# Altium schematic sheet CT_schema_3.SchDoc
size 362 x 192 mm
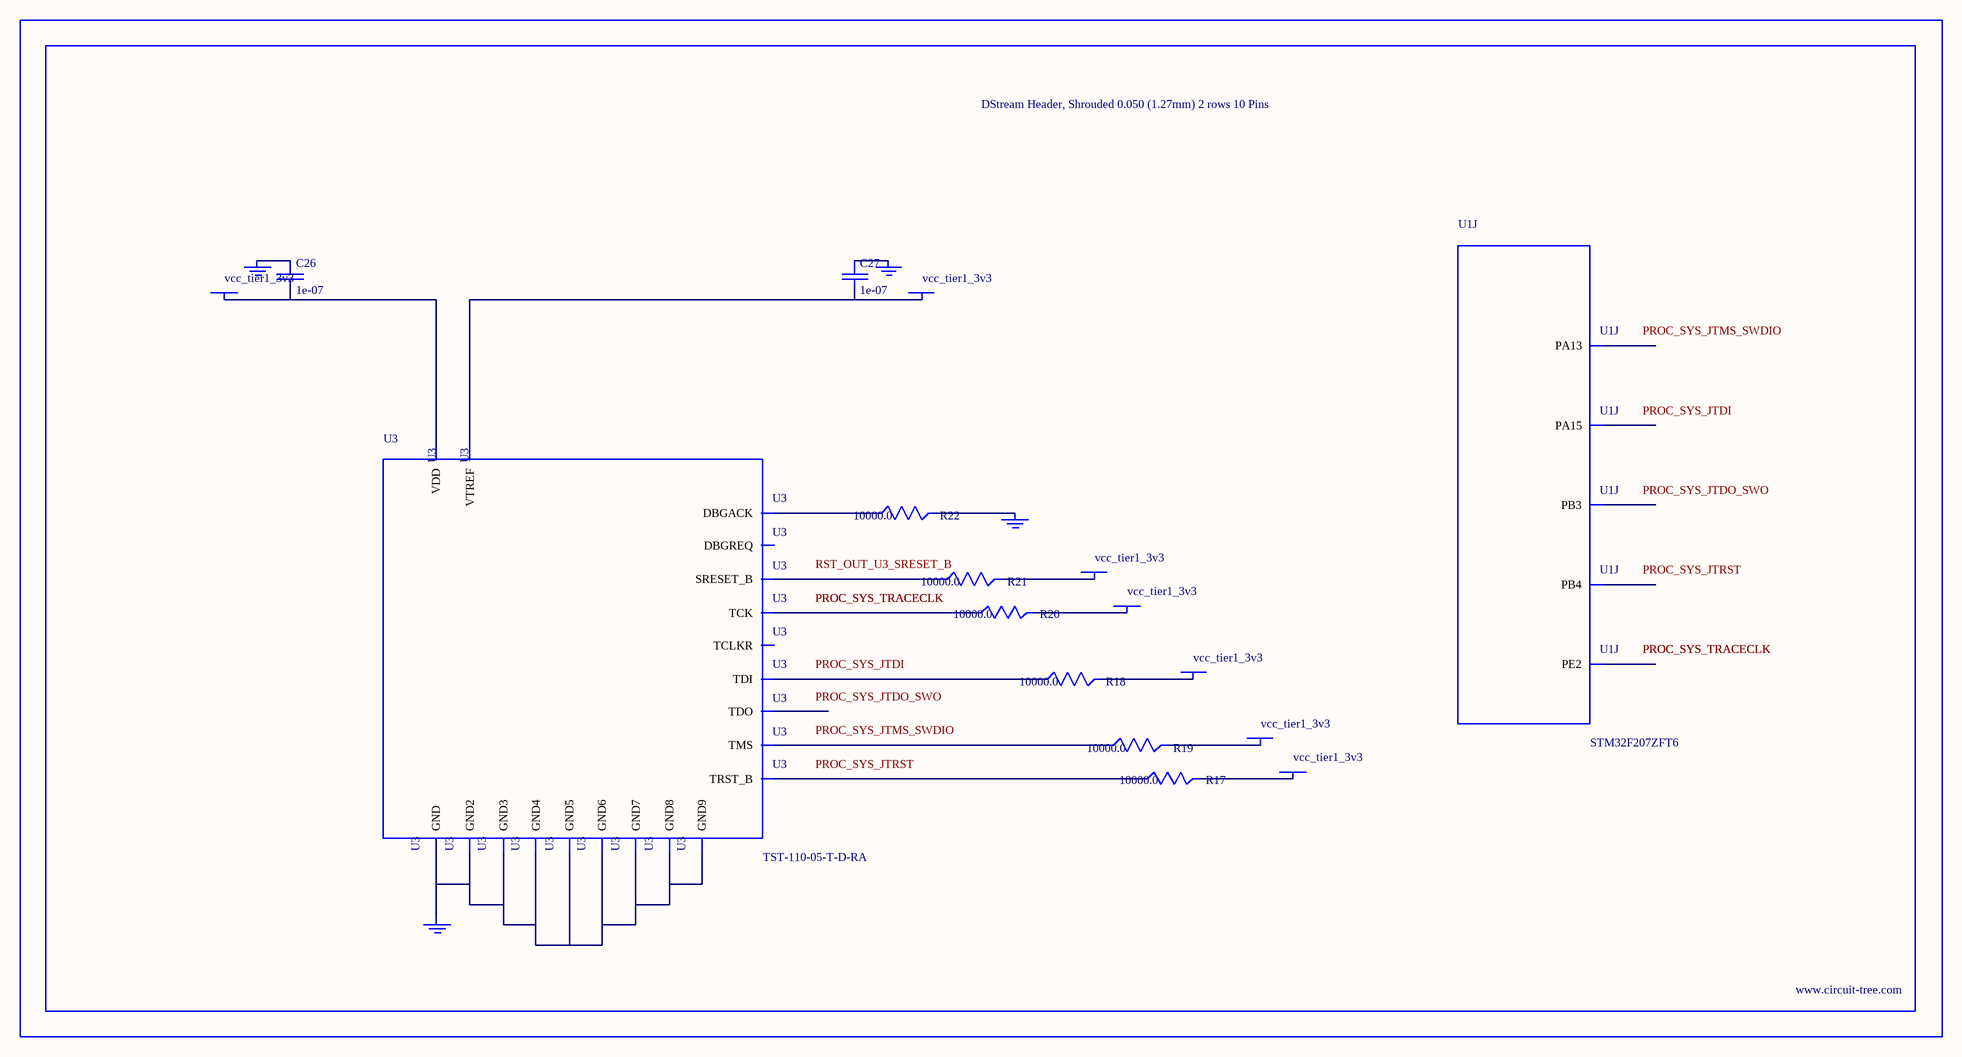
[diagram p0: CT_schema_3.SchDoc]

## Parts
BORDER2  (no value)
C26  1e-07  [C0402]
C27  1e-07  [C0402]
GND_INSTANCE_2_0  (no value)
GND_INSTANCE_2_1  (no value)
GND_INSTANCE_2_2  (no value)
GND_INSTANCE_2_3  (no value)
POWER_INSTANCE_2_0  vcc_tier1_3v3
POWER_INSTANCE_2_1  vcc_tier1_3v3
POWER_INSTANCE_2_2  vcc_tier1_3v3
POWER_INSTANCE_2_3  vcc_tier1_3v3
POWER_INSTANCE_2_4  vcc_tier1_3v3
POWER_INSTANCE_2_5  vcc_tier1_3v3
POWER_INSTANCE_2_6  vcc_tier1_3v3
R17  10000.0  [R0603]
R18  10000.0  [R0603]
R19  10000.0  [R0603]
R20  10000.0  [R0603]
R21  10000.0  [R0603]
R22  10000.0  [R0603]
U1  STM32F207ZFT6  [LQFP144]  (part J of 13)
U3  TST-110-05-T-D-RA  [TST-110-05-T-D-RA]

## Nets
NetC26_1: C26.1 GND_INSTANCE_2_1.0(GND)
NetC26_2: C26.2 POWER_INSTANCE_2_1.0(PWR) U3.2(VDD)
NetC27_1: C27.1 GND_INSTANCE_2_0.0(GND)
NetC27_2: C27.2 POWER_INSTANCE_2_0.0(PWR) U3.1(VTREF)
NetGND_INSTANCE_2_2_0: GND_INSTANCE_2_2.0(GND) R22.2
NetGND_INSTANCE_2_3_0: GND_INSTANCE_2_3.0(GND) U3.4(GND) U3.6(GND2) U3.8(GND3) U3.10(GND4) U3.12(GND5) U3.14(GND6) U3.16(GND7) U3.18(GND8) U3.20(GND9)
NetPOWER_INSTANCE_2_2_0: POWER_INSTANCE_2_2.0(PWR) R17.2
NetPOWER_INSTANCE_2_3_0: POWER_INSTANCE_2_3.0(PWR) R18.2
NetPOWER_INSTANCE_2_4_0: POWER_INSTANCE_2_4.0(PWR) R19.2
NetPOWER_INSTANCE_2_5_0: POWER_INSTANCE_2_5.0(PWR) R20.2
NetPOWER_INSTANCE_2_6_0: POWER_INSTANCE_2_6.0(PWR) R21.2
NetR17_1: R17.1 U3.3(TRST_B)
NetR18_1: R18.1 U3.5(TDI)
NetR19_1: R19.1 U3.7(TMS)
NetR20_1: R20.1 U3.9(TCK)
NetR21_1: R21.1 U3.15(SRESET_B)
NetR22_1: R22.1 U3.19(DBGACK)

Not connected (* = marked no-connect by the designer): U1 1(PE2) 105(PA13) 110(PA15) 133(PB3) 134(PB4); U3 11(TCLKR) 13(TDO) 17(DBGREQ)

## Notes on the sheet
- Labels drawn without touching a wire or pin: PROC_SYS_JTDI, PROC_SYS_JTDO_SWO, PROC_SYS_JTMS_SWDIO, PROC_SYS_JTRST, RST_OUT_U3_SRESET_B

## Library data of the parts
BORDER2 = BORDER_PAGE2
C26 C27 = C0402C104K3RACTU
GND_INSTANCE_2_0-GND_INSTANCE_2_3 = GND
POWER_INSTANCE_2_0-POWER_INSTANCE_2_6 = PWR
R17-R22 = RC0603JR-0710KL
